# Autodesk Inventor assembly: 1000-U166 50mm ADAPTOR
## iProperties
Created: 2007-03
Part Number: 1000-U166 50mm ADAPTOR
Document SubType Name: Assembly
Designer: Andy Moles
Translation Standard: STEP AP214IS
File Name: 1000-U166_ASM
Preprocessor: PRO/ENGINEER BY PARAMETRIC TECHNOLOGY CORPORATION, 2003200
Postprocessor: Build: 344b, Release: 11 SP2 - Date: Fri 08/18/2006
Sent Units: MILLIMETERS
Uncertainty: 0.005122590958887999
Author: Andy Moles
